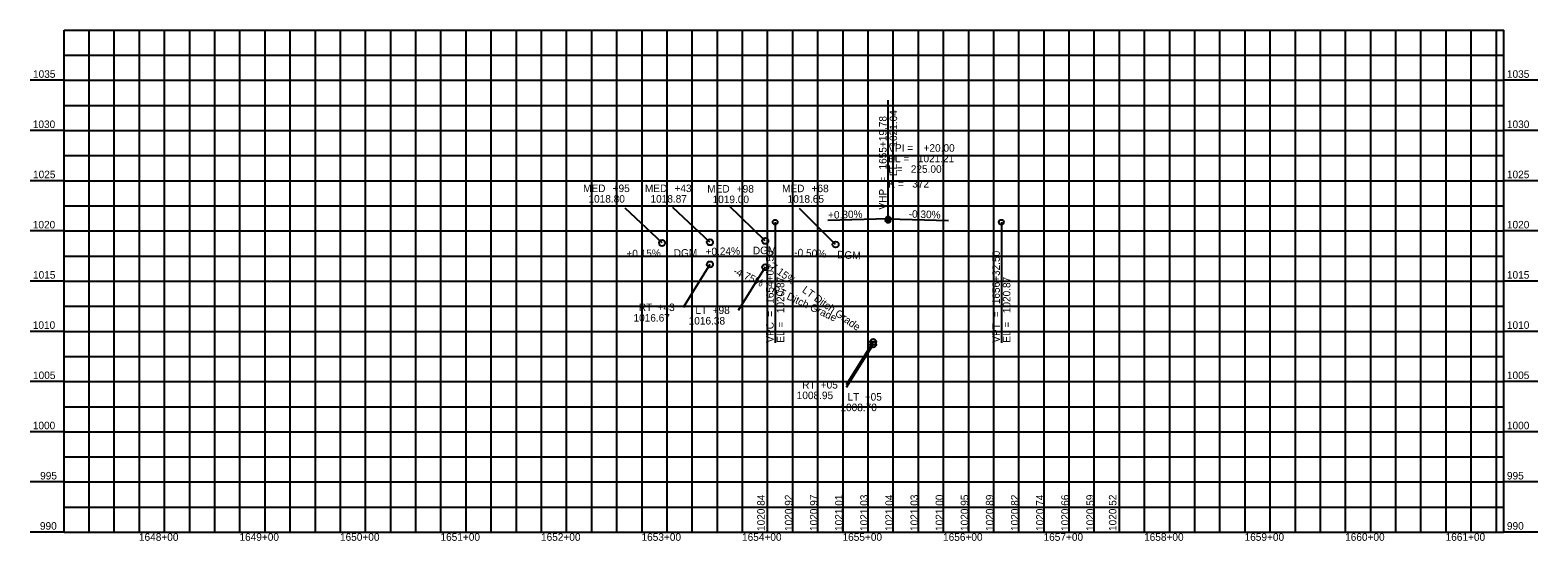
# Model space of a CAD drawing. Extents: x 4442 to 5942, y 981 to 1490.
import ezdxf

# ---------------------------------------------------------------- set-up
doc = ezdxf.new("R2010")
doc.units = 0
for name, color, linetype in [('Profile', 7, 'Continuous'), ('SheetBorder', 7, 'Continuous'), ('SheetGridMajor', 7, 'Continuous'), ('SheetGridMinor', 7, 'Continuous'), ('Text', 7, 'Continuous'), ('TextAlignment', 7, 'Continuous')]:
    doc.layers.add(name, color=color, linetype=linetype)

msp = doc.modelspace()

# ---------------------------------------------------------------- linework, layer by layer
at = {"layer": 'Profile'}
for p, q in [((5070.3, 1278), (5033.5, 1312.7)), ((5117.9, 1278.7), (5080.9, 1313.2)), ((5172.9, 1280), (5136.6, 1315.3)), ((5242.9, 1276.5), (5207, 1312.2))]:
    msp.add_line(p, q, dxfattribs=at)
for centre in [(5070.3, 1278), (5117.9, 1278.7), (5172.9, 1280), (5242.9, 1276.5)]:
    msp.add_circle(centre, 3, dxfattribs=at)
at = {"layer": 'SheetBorder'}
for p, q in [((4475.3, 1490), (5907.8, 1490)), ((4475.3, 990), (4475.3, 1490)), ((5907.8, 990), (5907.8, 1490)), ((4475.3, 990), (5907.8, 990))]:
    msp.add_line(p, q, dxfattribs=at)
at = {"layer": 'SheetGridMajor'}
for p, q in [((4575.3, 990), (4575.3, 1490)), ((4675.3, 990), (4675.3, 1490)), ((4775.3, 990), (4775.3, 1490)), ((4875.3, 990), (4875.3, 1490)), ((4975.3, 990), (4975.3, 1490)), ((5075.3, 990), (5075.3, 1490)), ((5175.3, 990), (5175.3, 1490)), ((5275.3, 990), (5275.3, 1490)), ((5375.3, 990), (5375.3, 1490)), ((5475.3, 990), (5475.3, 1490)), ((5575.3, 990), (5575.3, 1490)), ((5675.3, 990), (5675.3, 1490)), ((5775.3, 990), (5775.3, 1490)), ((5875.3, 990), (5875.3, 1490)), ((4475.3, 1440), (4441.6, 1440)), ((4475.3, 1440), (5907.8, 1440)), ((5941.6, 1440), (5907.8, 1440)), ((4475.3, 1390), (4441.6, 1390)), ((4475.3, 1390), (5907.8, 1390)), ((5941.6, 1390), (5907.8, 1390)), ((4475.3, 1340), (4441.6, 1340)), ((4475.3, 1340), (5907.8, 1340)), ((5941.6, 1340), (5907.8, 1340)), ((4475.3, 1290), (4441.6, 1290)), ((4475.3, 1290), (5907.8, 1290)), ((5941.6, 1290), (5907.8, 1290)), ((4475.3, 1240), (4441.6, 1240)), ((4475.3, 1240), (5907.8, 1240)), ((5941.6, 1240), (5907.8, 1240)), ((4475.3, 1190), (4441.6, 1190)), ((4475.3, 1190), (5907.8, 1190)), ((5941.6, 1190), (5907.8, 1190)), ((4475.3, 1140), (4441.6, 1140)), ((4475.3, 1140), (5907.8, 1140)), ((5941.6, 1140), (5907.8, 1140)), ((4475.3, 1090), (4441.6, 1090)), ((4475.3, 1090), (5907.8, 1090)), ((5941.6, 1090), (5907.8, 1090)), ((4475.3, 1040), (4441.6, 1040)), ((4475.3, 1040), (5907.8, 1040)), ((5941.6, 1040), (5907.8, 1040)), ((4475.3, 990), (4441.6, 990)), ((5941.6, 990), (5907.8, 990))]:
    msp.add_line(p, q, dxfattribs=at)
at = {"layer": 'SheetGridMinor'}
for p, q in [((4500.3, 990), (4500.3, 1490)), ((4525.3, 990), (4525.3, 1490)), ((4550.3, 990), (4550.3, 1490)), ((4600.3, 990), (4600.3, 1490)), ((4625.3, 990), (4625.3, 1490)), ((4650.3, 990), (4650.3, 1490)), ((4700.3, 990), (4700.3, 1490)), ((4725.3, 990), (4725.3, 1490)), ((4750.3, 990), (4750.3, 1490)), ((4800.3, 990), (4800.3, 1490)), ((4825.3, 990), (4825.3, 1490)), ((4850.3, 990), (4850.3, 1490)), ((4900.3, 990), (4900.3, 1490)), ((4925.3, 990), (4925.3, 1490)), ((4950.3, 990), (4950.3, 1490)), ((5000.3, 990), (5000.3, 1490)), ((5025.3, 990), (5025.3, 1490)), ((5050.3, 990), (5050.3, 1490)), ((5100.3, 990), (5100.3, 1490)), ((5125.3, 990), (5125.3, 1490)), ((5150.3, 990), (5150.3, 1490)), ((5200.3, 990), (5200.3, 1490)), ((5225.3, 990), (5225.3, 1490)), ((5250.3, 990), (5250.3, 1490)), ((5300.3, 990), (5300.3, 1490)), ((5325.3, 990), (5325.3, 1490)), ((5350.3, 990), (5350.3, 1490)), ((5400.3, 990), (5400.3, 1490)), ((5425.3, 990), (5425.3, 1490)), ((5450.3, 990), (5450.3, 1490)), ((5500.3, 990), (5500.3, 1490)), ((5525.3, 990), (5525.3, 1490)), ((5550.3, 990), (5550.3, 1490)), ((5600.3, 990), (5600.3, 1490)), ((5625.3, 990), (5625.3, 1490)), ((5650.3, 990), (5650.3, 1490)), ((5700.3, 990), (5700.3, 1490)), ((5725.3, 990), (5725.3, 1490)), ((5750.3, 990), (5750.3, 1490)), ((5800.3, 990), (5800.3, 1490)), ((5825.3, 990), (5825.3, 1490)), ((5850.3, 990), (5850.3, 1490)), ((5900.3, 990), (5900.3, 1490)), ((4475.3, 1465), (5907.8, 1465)), ((4475.3, 1415), (5907.8, 1415)), ((4475.3, 1365), (5907.8, 1365)), ((4475.3, 1315), (5907.8, 1315)), ((4475.3, 1265), (5907.8, 1265)), ((4475.3, 1215), (5907.8, 1215)), ((4475.3, 1165), (5907.8, 1165)), ((4475.3, 1115), (5907.8, 1115)), ((4475.3, 1065), (5907.8, 1065)), ((4475.3, 1015), (5907.8, 1015))]:
    msp.add_line(p, q, dxfattribs=at)
at = {"layer": 'Text'}
for centre in [(5182.8, 1298.7), (5295.3, 1302.1), (5407.8, 1298.7)]:
    msp.add_circle(centre, 2.43, dxfattribs=at)
at = {"layer": 'TextAlignment'}
for p, q in [((5295.1, 1300.4), (5295.1, 1420.4)), ((5182.8, 1298.7), (5182.8, 1298.7)), ((5182.8, 1298.7), (5182.8, 1178.7)), ((5295.3, 1302.1), (5235.3, 1300.3)), ((5295.3, 1302.1), (5295.3, 1302.1)), ((5295.3, 1302.1), (5355.3, 1300.3)), ((5407.8, 1298.7), (5407.8, 1298.7)), ((5407.8, 1298.7), (5407.8, 1178.7)), ((5117.9, 1256.7), (5091.1, 1213.8)), ((5172.9, 1253.8), (5146.1, 1210.9)), ((5280.3, 1179.5), (5253.5, 1136.6)), ((5280.3, 1177), (5253.5, 1134.1))]:
    msp.add_line(p, q, dxfattribs=at)
for centre, radius in [((5295.1, 1300.4), 2.43), ((5117.9, 1256.7), 3), ((5172.9, 1253.8), 3), ((5280.3, 1179.5), 3), ((5280.3, 1177), 3)]:
    msp.add_circle(centre, radius, dxfattribs=at)

# ---------------------------------------------------------------- texts
at = {"layer": 'Profile'}
for s, p in [('MED ', (4991.7, 1328.7)), ('+95', (5021.1, 1328.7)), ('MED ', (5053.2, 1328.7)), ('+43', (5082.6, 1328.7)), ('MED ', (5115.2, 1328.2)), ('+98', (5144.6, 1328.2)), ('MED ', (5189.6, 1328.6)), ('+68', (5219, 1328.6)), ('1018.80', (4997, 1318.2)), ('1018.87', (5058.7, 1318.2)), ('1019.00', (5120.5, 1317.7)), ('1018.65', (5195.1, 1318.1))]:
    msp.add_text(s, height=7.5, dxfattribs=at).set_placement(p)
for s, rotation, p in [('+0.15%', 0.8611, (5034.8, 1263.6)), (' DGM', 0.8611, (5079.1, 1264.2)), ('+0.24%', 1.3683, (5113.6, 1265.6)), (' DGM', 1.3683, (5157.9, 1266.6)), ('-0.50%', 357.1425, (5201.6, 1265)), (' DGM', 357.1425, (5241.5, 1263))]:
    msp.add_text(s, height=7.5, rotation=rotation, dxfattribs=at).set_placement(p)
at = {"layer": 'Text'}
for s, p in [('1020.84', (5172.4, 991.2)), ('1020.92', (5199.9, 991.2)), ('1020.97', (5224.9, 991.2)), ('1021.01', (5249.9, 991.2)), ('1021.03', (5274.9, 991.2)), ('1021.04', (5299.9, 991.2)), ('1021.03', (5324.9, 991.2)), ('1021.00', (5349.9, 991.2)), ('1020.95', (5374.9, 991.2)), ('1020.89', (5399.9, 991.2)), ('1020.82', (5424.9, 991.2)), ('1020.74', (5449.9, 991.2)), ('1020.66', (5474.9, 991.2)), ('1020.59', (5499.9, 991.2)), ('1020.52', (5522.3, 991.2))]:
    msp.add_text(s, height=7.5, rotation=90, dxfattribs=at).set_placement(p)
at = {"layer": 'TextAlignment'}
for s, p in [('1035', (4444.4, 1442.5)), ('1035', (5910.8, 1442.5)), ('1030', (4444.2, 1392.5)), ('1030', (5910.8, 1392.5)), ('VPI = ', (5295.3, 1368.9)), ('EL = ', (5295.3, 1358.4)), ('1021.21', (5324.7, 1358.4)), ('+20.00', (5330.4, 1368.9)), ('1025', (4444.4, 1342.5)), ('L = ', (5295.3, 1347.9)), ("225.00'", (5317.7, 1347.9)), ('1025', (5910.8, 1342.5)), ('K = ', (5295.3, 1333.2)), ('372', (5319.1, 1333.2)), ('1020', (4444.2, 1292.5)), ('1020', (5910.8, 1292.5)), ('1015', (4444.4, 1242.5)), ('1015', (5910.8, 1242.5)), ('RT ', (5047.2, 1210.2)), ('+43', (5065.8, 1210.2)), ('1010', (4444.2, 1192.5)), ('1016.67', (5041.8, 1199.7)), ('1016.38', (5096.7, 1196.8)), ('LT ', (5103.4, 1207.3)), ('+98', (5120.6, 1207.3)), ('1010', (5910.8, 1192.5)), ('1005', (4444.4, 1142.5)), ('RT ', (5209.6, 1133)), ('+05', (5228.1, 1133)), ('1005', (5910.8, 1142.5)), ('1008.95', (5204.2, 1122.5)), ('LT ', (5254.7, 1121)), ('+05', (5271.9, 1121)), ('1008.70', (5247.7, 1110.5)), ('1000', (4444.2, 1092.5)), ('1000', (5910.8, 1092.5)), ('995', (4451.5, 1042.5)), ('995', (5910.8, 1042.5)), ('990', (4451.3, 992.5)), ('990', (5910.8, 992.5)), ('1648+00', (4549.8, 981.4)), ('1649+00', (4649.8, 981.4)), ('1650+00', (4749.8, 981.4)), ('1651+00', (4849.8, 981.4)), ('1652+00', (4949.8, 981.4)), ('1653+00', (5049.8, 981.4)), ('1654+00', (5149.8, 981.4)), ('1655+00', (5249.8, 981.4)), ('1656+00', (5349.8, 981.4)), ('1657+00', (5449.8, 981.4)), ('1658+00', (5549.8, 981.4)), ('1659+00', (5649.8, 981.4)), ('1660+00', (5749.8, 981.4)), ('1661+00', (5849.8, 981.4))]:
    msp.add_text(s, height=7.5, dxfattribs=at).set_placement(p)
for s, rotation, p in [('1655+19.78', 90, (5293.6, 1351.2)), ('1021.04', 90, (5304.1, 1374)), ('EL = ', 90, (5304.1, 1344.6)), (' = ', 90, (5293.6, 1335.4)), ('VHP', 90, (5293.6, 1311.3)), ('+0.30%', 1.7312, (5235.5, 1302.1)), ('-0.30%', 358.2622, (5315.5, 1303.3)), ('1654+07.50', 90, (5181.3, 1217.5)), ('1656+32.50', 90, (5406.3, 1217)), ('-4.75%', 334.5877, (5140.3, 1247.7)), ('-7.15%', 324.4195, (5174.2, 1254.6)), (' RT Ditch Grade', 334.5877, (5176.4, 1230.5)), ('1020.87', 90, (5191.8, 1208.1)), (' LT Ditch Grade', 324.4195, (5206.7, 1231.3)), ('1020.87', 90, (5416.8, 1208.1)), (' = ', 90, (5181.3, 1201.8)), (' = ', 90, (5406.3, 1201.2)), ('VPC', 90, (5181.3, 1178.7)), ('EL = ', 90, (5191.8, 1178.7)), ('VPT', 90, (5406.3, 1178.7)), ('EL = ', 90, (5416.8, 1178.7))]:
    msp.add_text(s, height=7.5, rotation=rotation, dxfattribs=at).set_placement(p)

doc.saveas('drawing.dxf')
